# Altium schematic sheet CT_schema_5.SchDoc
size 226 x 258 mm
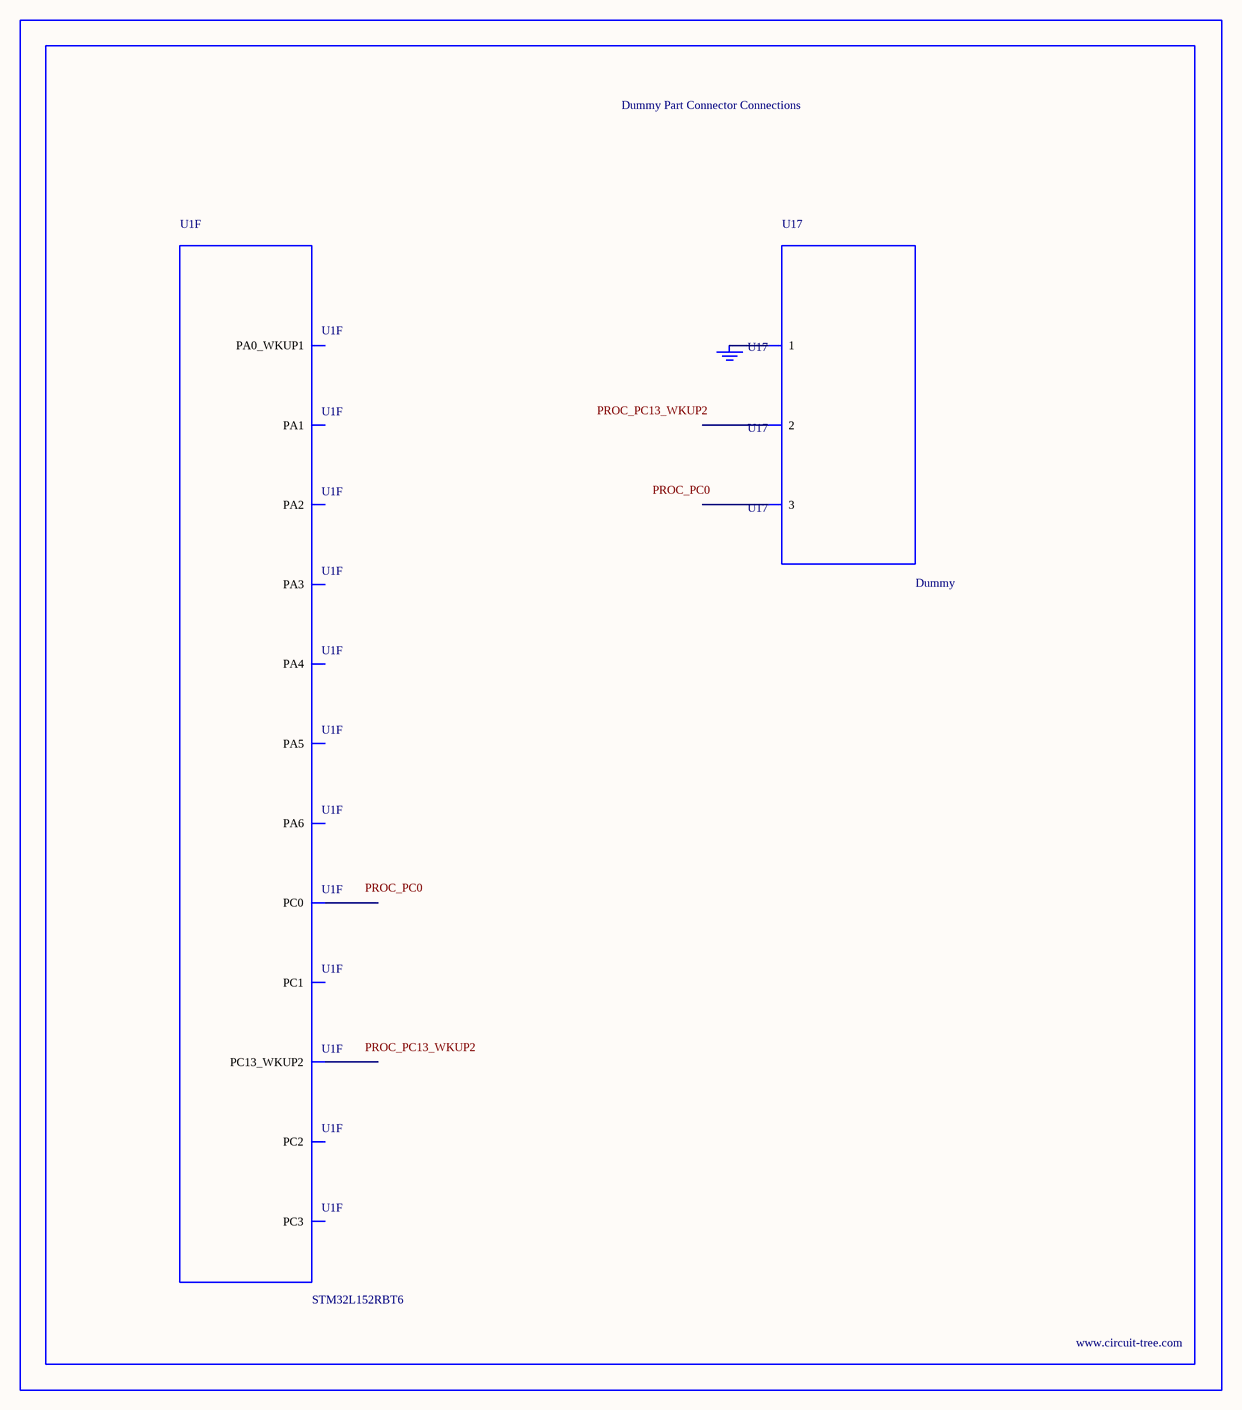
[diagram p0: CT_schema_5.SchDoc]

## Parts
BORDER4  (no value)
GND_INSTANCE_4_0  (no value)
U1  STM32L152RBT6  [LQFP64]  (part F of 6)
U17  Dummy  [DUMMY_PACKAGE_139]

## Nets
NetGND_INSTANCE_4_0_0: GND_INSTANCE_4_0.0(GND) U17.1

Not connected (* = marked no-connect by the designer): U1 2(PC13_WKUP2) 8(PC0) 9(PC1) 10(PC2) 11(PC3) 14(PA0_WKUP1) 15(PA1) 16(PA2) 17(PA3) 20(PA4) 21(PA5) 22(PA6); U17 2 3

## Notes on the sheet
- Labels drawn without touching a wire or pin: PROC_PC0, PROC_PC13_WKUP2

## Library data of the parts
BORDER4 = BORDER_PAGE4
GND_INSTANCE_4_0 = GND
